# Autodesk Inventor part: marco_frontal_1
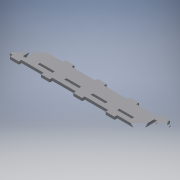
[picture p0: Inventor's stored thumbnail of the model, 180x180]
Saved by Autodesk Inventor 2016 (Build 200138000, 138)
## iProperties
Created: 2017-06
Part Number: marco_frontal_1
Material: Generic
Document SubType Name: Modeling
Designer: laboratorioesan
Density: 1 g/cm^3
Appearance: Default
Author: laboratorioesan
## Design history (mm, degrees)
sketch "Sketch1"
  geometry: L1 (440, 0)-(440, 15.5) reference; L2 (440, 15.5)-(540, 15.5) reference; L3 (540, 15.5)-(540, 0) reference; L4 (540, 0)-(440, 0) reference; L5 (80, 0)-(80, 15.5) reference; L6 (80, 15.5)-(180, 15.5) reference; L7 (180, 15.5)-(180, 0) reference; L8 (180, 0)-(80, 0) reference; L9 (260, 0)-(260, 15.5) reference; L10 (260, 15.5)-(360, 15.5) reference; L11 (360, 15.5)-(360, 0) reference; L12 (360, 0)-(260, 0) reference; L13 (620, 0)-(620, 15.5) reference; L14 (620, 15.5)-(720, 15.5) reference; L15 (720, 15.5)-(720, 0) reference; L16 (720, 0)-(620, 0) reference; L17 (-18.5, -2.5)-(-18.5, 72.5) reference; L18 (-18.5, 72.5)-(0, 72.5) reference; L19 (0, 72.5)-(0, -2.5) reference; L20 (0, -2.5)-(-18.5, -2.5) reference; L21 (818.5, -2.5)-(800, -2.5) reference; L22 (800, -2.5)-(800, 72.5) reference; L23 (800, 72.5)-(818.5, 72.5) reference; L24 (818.5, 72.5)-(818.5, -2.5) reference; L25 (-38.5, -30)-(838.5, -30) reference; L26 (838.5, -30)-(838.5, 100) reference; L27 (838.5, 100)-(-38.5, 100) reference; L28 (-38.5, 100)-(-38.5, -30) reference; L29 (440, 0)-(440, 15.5) reference; L30 (440, 15.5)-(540, 15.5) reference; L31 (540, 15.5)-(540, 0) reference; L32 (540, 0)-(440, 0) reference; L33 (80, 0)-(80, 15.5) reference; L34 (80, 15.5)-(180, 15.5) reference; L35 (180, 15.5)-(180, 0) reference; L36 (180, 0)-(80, 0) reference; L37 (260, 0)-(260, 15.5) reference; L38 (260, 15.5)-(360, 15.5) reference; L39 (360, 15.5)-(360, 0) reference; L40 (360, 0)-(260, 0) reference; L41 (620, 0)-(620, 15.5) reference; L42 (620, 15.5)-(720, 15.5) reference; L43 (720, 15.5)-(720, 0) reference; L44 (720, 0)-(620, 0) reference; L45 (-18.5, -2.5)-(-18.5, 72.5) reference; L46 (-18.5, 72.5)-(0, 72.5) reference; L47 (0, 72.5)-(0, -2.5) reference; L48 (0, -2.5)-(-18.5, -2.5) reference; L49 (818.5, -2.5)-(800, -2.5) reference; L50 (800, -2.5)-(800, 72.5) reference; L51 (800, 72.5)-(818.5, 72.5) reference; L52 (818.5, 72.5)-(818.5, -2.5) reference; L53 (-38.5, -30)-(838.5, -30) reference; L54 (838.5, -30)-(838.5, 100) reference; L55 (838.5, 100)-(-38.5, 100) reference; L56 (-38.5, 100)-(-38.5, -30) reference; L57 (892.636, 118.5)-(930, 118.5) reference; L58 (930, 100)-(930, 118.5) reference; L59 (-130, 118.5)-(-130, 100) reference; L60 (-130, 100)-(930, 100); L61 (930, 100)-(930, -30); L62 (930, -30)-(-130, -30); L63 (-130, -30)-(-130, 100); L64 (-60, 100)-(0, 100)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; 2 further points
  constraints: 88 end point, 22 parallel, 15 point on line, 11 horizontal, 11 perpendicular, 4 horizontal alignment, 1 midpoint, 1 vertical alignment
  dimensions: "d0" = 60 distance of L66.end L65.end; "d1" = 18 distance of L65.end L64.end; "d2" = 60 distance of L69.end L70.end; "d3" = 60 distance of L73.end L74.end; "d4" = 60 distance of L77.end L78.end; "d5" = 60 distance of L81.end L82.end; "d6" = 70 distance of L59.end L64.start; "d7" = 150 distance of L70.end L64.end; "d8" = 70 distance of L60.end L81.end; "d9" = 150 distance of L82.end L77.end; "d10" = 160 distance of L78.end L73.end; "d13" = 18 distance of L84.end L85.end
extrude "Extrusion2" new body sketch "Sketch1" distance "d14" = 18.5; taper "d15" = 0 deg
sketch "Sketch2"
  geometry: L1 (620, 0)-(620, 15.5) reference; L2 (620, 15.5)-(720, 15.5) reference; L3 (720, 15.5)-(720, 0) reference; L4 (720, 0)-(620, 0) reference; L5 (260, 0)-(260, 15.5) reference; L6 (260, 15.5)-(360, 15.5) reference; L7 (360, 15.5)-(360, 0) reference; L8 (360, 0)-(260, 0) reference; L9 (80, 0)-(80, 15.5) reference; L10 (80, 15.5)-(180, 15.5) reference; L11 (180, 15.5)-(180, 0) reference; L12 (180, 0)-(80, 0) reference; L13 (440, 0)-(440, 15.5) reference; L14 (440, 15.5)-(540, 15.5) reference; L15 (540, 15.5)-(540, 0) reference; L16 (540, 0)-(440, 0) reference; L17 (818.5, -2.5)-(800, -2.5) reference; L18 (800, -2.5)-(800, 72.5) reference; L19 (800, 72.5)-(818.5, 72.5) reference; L20 (818.5, 72.5)-(818.5, -2.5) reference; L21 (-18.5, -2.5)-(-18.5, 72.5) reference; L22 (-18.5, 72.5)-(0, 72.5) reference; L23 (0, 72.5)-(0, -2.5) reference; L24 (0, -2.5)-(-18.5, -2.5) reference; L25 (150, -30)-(150, -48) reference; L26 (150, -48)-(210, -48) reference; L27 (210, -48)-(210, -30) reference; L28 (210, -30)-(370, -30) reference; L29 (370, -30)-(370, -48) reference; L30 (370, -48)-(430, -48) reference; L31 (430, -48)-(430, -30) reference; L32 (430, -30)-(590, -30) reference; L33 (590, -30)-(590, -48) reference; L34 (590, -48)-(650, -48) reference; L35 (650, -48)-(650, -30) reference; L36 (650, -30)-(800, -30) reference; L37 (800, -30)-(800, -48) reference; L38 (800, -48)-(860, -48) reference; L39 (860, -48)-(860, -30) reference; L40 (860, -30)-(930, -30) reference; L41 (930, -30)-(930, 100) reference; L42 (930, 100)-(860, 100) reference; L43 (860, 100)-(860, 118) reference; L44 (860, 118)-(800, 118) reference; L45 (800, 118)-(800, 100) reference; L46 (800, 100)-(650, 100) reference; L47 (650, 100)-(650, 118) reference; L48 (650, 118)-(590, 118) reference; L49 (590, 118)-(590, 100) reference; L50 (590, 100)-(430, 100) reference; L51 (430, 100)-(430, 118) reference; L52 (430, 118)-(370, 118) reference; L53 (370, 118)-(370, 100) reference; L54 (370, 100)-(210, 100) reference; L55 (210, 100)-(210, 118) reference; L56 (210, 118)-(150, 118) reference; L57 (150, 118)-(150, 100) reference; L58 (150, 100)-(0, 100) reference; L59 (0, 100)-(0, 118) reference; L60 (0, 118)-(-60, 118) reference; L61 (-60, 118)-(-60, 100) reference; L62 (-60, 100)-(-130, 100) reference; L63 (-130, 100)-(-130, -30) reference; L64 (-130, -30)-(-60, -30) reference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; 1 further point
  constraints: 16 end point, 4 parallel, 2 horizontal, 2 midpoint, 2 perpendicular
extrude "Extrusion3" cut sketch "Sketch2" distance "d16" = 18.5; taper "d17" = 0 deg
sketch "Sketch3"
  geometry: L1 (848.5, -30)-(848.5, 100) reference; L2 (895, -30)-(895, 100) reference; L3 (895, 100)-(860, 100) reference; L4 (860, 100)-(860, 118) reference; L5 (860, 118)-(800, 118) reference; L6 (800, 118)-(800, 100) reference; L7 (800, 100)-(650, 100) reference; L8 (650, 100)-(650, 118) reference; L9 (650, 118)-(590, 118) reference; L10 (590, 118)-(590, 100) reference; L11 (590, 100)-(430, 100) reference; L12 (430, 100)-(430, 118) reference; L13 (430, 118)-(370, 118) reference; L14 (370, 118)-(370, 100) reference; L15 (370, 100)-(210, 100) reference; L16 (210, 100)-(210, 118) reference; L17 (210, 118)-(150, 118) reference; L18 (150, 118)-(150, 100) reference; L19 (150, 100)-(0, 100) reference; L20 (0, 100)-(0, 118) reference; L21 (0, 118)-(-60, 118) reference; L22 (-60, 118)-(-60, 100) reference; L23 (-60, 100)-(-95, 100) reference; L24 (-95, 100)-(-95, -30) reference; L25 (-95, -30)-(-60, -30) reference; L26 (-60, -30)-(-60, -48) reference; L27 (-60, -48)-(0, -48) reference; L28 (0, -48)-(0, -30) reference; L29 (0, -30)-(150, -30) reference; L30 (150, -30)-(150, -48) reference; L31 (150, -48)-(210, -48) reference; L32 (210, -48)-(210, -30) reference; L33 (210, -30)-(370, -30) reference; L34 (370, -30)-(370, -48) reference; L35 (370, -48)-(430, -48) reference; L36 (430, -48)-(430, -30) reference; L37 (430, -30)-(590, -30) reference; L38 (590, -30)-(590, -48) reference; L39 (590, -48)-(650, -48) reference; L40 (650, -48)-(650, -30) reference; L41 (650, -30)-(800, -30) reference; L42 (800, -30)-(800, -48) reference; L43 (800, -48)-(860, -48) reference; L44 (860, -48)-(860, -30) reference; L45 (860, -30)-(895, -30) reference; L46 (620, 0)-(620, 15.5) reference; L47 (620, 15.5)-(720, 15.5) reference; L48 (720, 15.5)-(720, 0) reference; L49 (720, 0)-(620, 0) reference; L50 (260, 0)-(260, 15.5) reference; L51 (260, 15.5)-(360, 15.5) reference; L52 (360, 15.5)-(360, 0) reference; L53 (360, 0)-(260, 0) reference; L54 (80, 0)-(80, 15.5) reference; L55 (80, 15.5)-(180, 15.5) reference; L56 (180, 15.5)-(180, 0) reference; L57 (180, 0)-(80, 0) reference; L58 (440, 0)-(440, 15.5) reference; L59 (440, 15.5)-(540, 15.5) reference; L60 (540, 15.5)-(540, 0) reference; L61 (540, 0)-(440, 0) reference; L62 (818.5, -2.5)-(800, -2.5) reference; L63 (800, -2.5)-(800, 72.5) reference; L64 (800, 72.5)-(818.5, 72.5) reference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; 1 further point
  constraints: 16 end point, 4 parallel, 2 horizontal, 2 perpendicular, 2 point on line
  dimensions: "d18" = 15 distance of L73.end L72.end; "d19" = 15 distance of L76.end L77.end
extrude "Extrusion4" cut sketch "Sketch3" distance "d20" = 18.5; taper "d21" = 0 deg
body "Solid2"
node "Reference1"
node "Reference2"
node "Reference3"
node "Reference4"
node "Reference5"
node "Projected Loop1"
node "Reference6"
node "Projected Loop2"
